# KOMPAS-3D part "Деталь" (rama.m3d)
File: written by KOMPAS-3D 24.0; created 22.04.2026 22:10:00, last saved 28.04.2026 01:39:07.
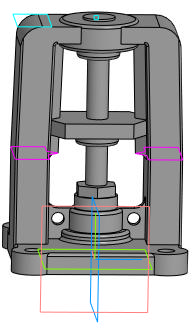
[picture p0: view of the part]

Document properties: Автор: mrdid; Полное имя файла: C:\Работа\ГОТОВЫЕ ИСХОДНИКИ\VSO2130M-F-S Клапан запорный сильфонный DN.ru Ду15-100 Ру40\исходные материалы\DN32\rama.m3d

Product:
- Part/product: Деталь
    Масса: 1.658725

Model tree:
1. Эскиз:2  (with: Ребро.Элемент выдавливания:14)
2. Элемент выдавливания:1
     Расстояние 1 = 10
3. Эскиз:3  (with: Грань.Элемент выдавливания:1, Ребро.Элемент выдавливания:1)
4. Элемент выдавливания:2
     Расстояние 2 = 10
5. Эскиз:4  (with: Грань.Элемент выдавливания:1)
6. Элемент выдавливания:3
     Расстояние 1 = 4.5
7. Эскиз:5  (with: Грань.Элемент выдавливания:3, Ребро.Элемент выдавливания:3)
8. Элемент выдавливания:4
     Расстояние 1 = 10
9. Эскиз:6  (with: Грань.Элемент выдавливания:1, Ребро.Элемент выдавливания:1)
10. Элемент выдавливания:5
     Расстояние 1 = 40
11. Эскиз:23  (with: Грань.Элемент выдавливания:4, Ребро.Элемент выдавливания:4)
12. Элемент выдавливания:21
     Расстояние 1 = 11
13. Эскиз:7  (with: Грань.Элемент выдавливания:21, Ребро.Элемент выдавливания:3)
14. Элемент выдавливания:6
     Расстояние 2 = 5
15. Эскиз:8  (with: Грань.Элемент выдавливания:5, Ребро.Элемент выдавливания:5)
16. Смещенная плоскость:1  (with: Грань.Элемент выдавливания:5)
17. Эскиз:9
18. Элемент по сечениям:1
19. Элемент по сечениям:2
20. Эскиз:10
21. Элемент выдавливания:8
     Расстояние 2 = 8
22. Эскиз:11  (with: Грань.Элемент выдавливания:8, Ребро.Элемент выдавливания:3)
23. Элемент выдавливания:9  (with: Грань.Элемент выдавливания:8)
     Расстояние 1 = 1; Расстояние 2 = 12; Смещение 2 = 4
24. Эскиз:12  (with: Грань.Элемент выдавливания:9, Ребро.Элемент выдавливания:9)
25. Элемент выдавливания:10
     Расстояние 1 = 5
26. Эскиз:13  (with: Грань.Элемент выдавливания:21, Ребро.Элемент выдавливания:3)
27. Элемент выдавливания:11  (with: Грань.Элемент выдавливания:10)
     Расстояние 1 = 59.988
28. Смещенная плоскость:2  (with: Грань.Элемент выдавливания:21)
29. Эскиз:14  (with: Ребро.Элемент по сечениям:2, Ребро.Элемент по сечениям:1)
30. Элемент выдавливания:12
     Расстояние 1 = 7
31. Эскиз:15  (with: Грань.Элемент выдавливания:12, Ребро.Элемент выдавливания:3)
32. Элемент выдавливания:13
     Расстояние 1 = 5
33. Эскиз:16  (with: Ребро.Элемент выдавливания:5, Ребро.Элемент выдавливания:1, Ребро.Элемент выдавливания:4)
34. Элемент выдавливания:14
     Расстояние 1 = 4
35. Элемент выдавливания:15
     Расстояние 1 = 2
36. Эскиз:17  (with: Ребро.Элемент выдавливания:5, Ребро.Элемент выдавливания:14)
37. Элемент выдавливания:16
     Расстояние 1 = 41
38. Скругление:1  (with: Ребро.Элемент выдавливания:1, Ребро.Элемент выдавливания:3)
     Радиус = 1.5
39. Скругление:2  (with: Ребро.Элемент выдавливания:9, Ребро.Элемент выдавливания:4, Ребро.Элемент выдавливания:13, Ребро.Элемент выдавливания:10)
40. Эскиз:18  (with: Грань.Элемент выдавливания:9)
41. Элемент выдавливания:17
     Расстояние 1 = 1
42. Скругление:3  (with: Ребро.Элемент по сечениям:2, Ребро.Элемент по сечениям:1)
     Радиус = 10
43. Скругление:4  (with: Ребро.Элемент выдавливания:8)
     Радиус = 1
44. Скругление:5  (with: Ребро.Элемент выдавливания:14)
     Радиус = 5
45. Эскиз:19  (with: Ребро.Элемент выдавливания:17)
46. Элемент выдавливания:18  (with: Грань.Элемент выдавливания:9)
     Смещение 1 = 5
47. Смещенная плоскость:3  (with: Грань.Элемент выдавливания:18)
     Расстояние = 2
48. Эскиз:20  (with: Ребро.Элемент выдавливания:18)
49. Элемент выдавливания:19
     Расстояние 2 = 0.2
50. Скругление:6  (with: Ребро.Элемент выдавливания:18)
     Радиус = 1
51. Эскиз:21  (with: Ребро.Элемент выдавливания:19)
52. Элемент выдавливания:20
     Расстояние 1 = 10
53. Скругление:7  (with: Ребро.Элемент по сечениям:2, Ребро.Элемент выдавливания:5, Ребро.Элемент по сечениям:1)
     Радиус = 1
54. Фаска:1  (with: Ребро.Элемент по сечениям:1, Ребро.Элемент по сечениям:2)
     Угол = 45; Длина 1 = 2; Длина 2 = 2
55. Массив по концентрической сетке:1  (with: Элемент выдавливания:2, Эскиз:3)  (labels: Клапан запорный DN.ru Ду32 Ру40)  (4 pattern instances)
     Шаг 2 = 360

Expressions: v249/2; DN/2
Referenced files in C:\Работа\ГОТОВЫЕ ИСХОДНИКИ\VSO2130M-F-S Клапан запорный сильфонный DN.ru Ду15-100 Ру40\исходные материалы\DN32\: VSO2130M-F-S Клапан запорный DN.ru Ду32 Ру40.a3d
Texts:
  DN+5
  Ось Y.Начало координат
